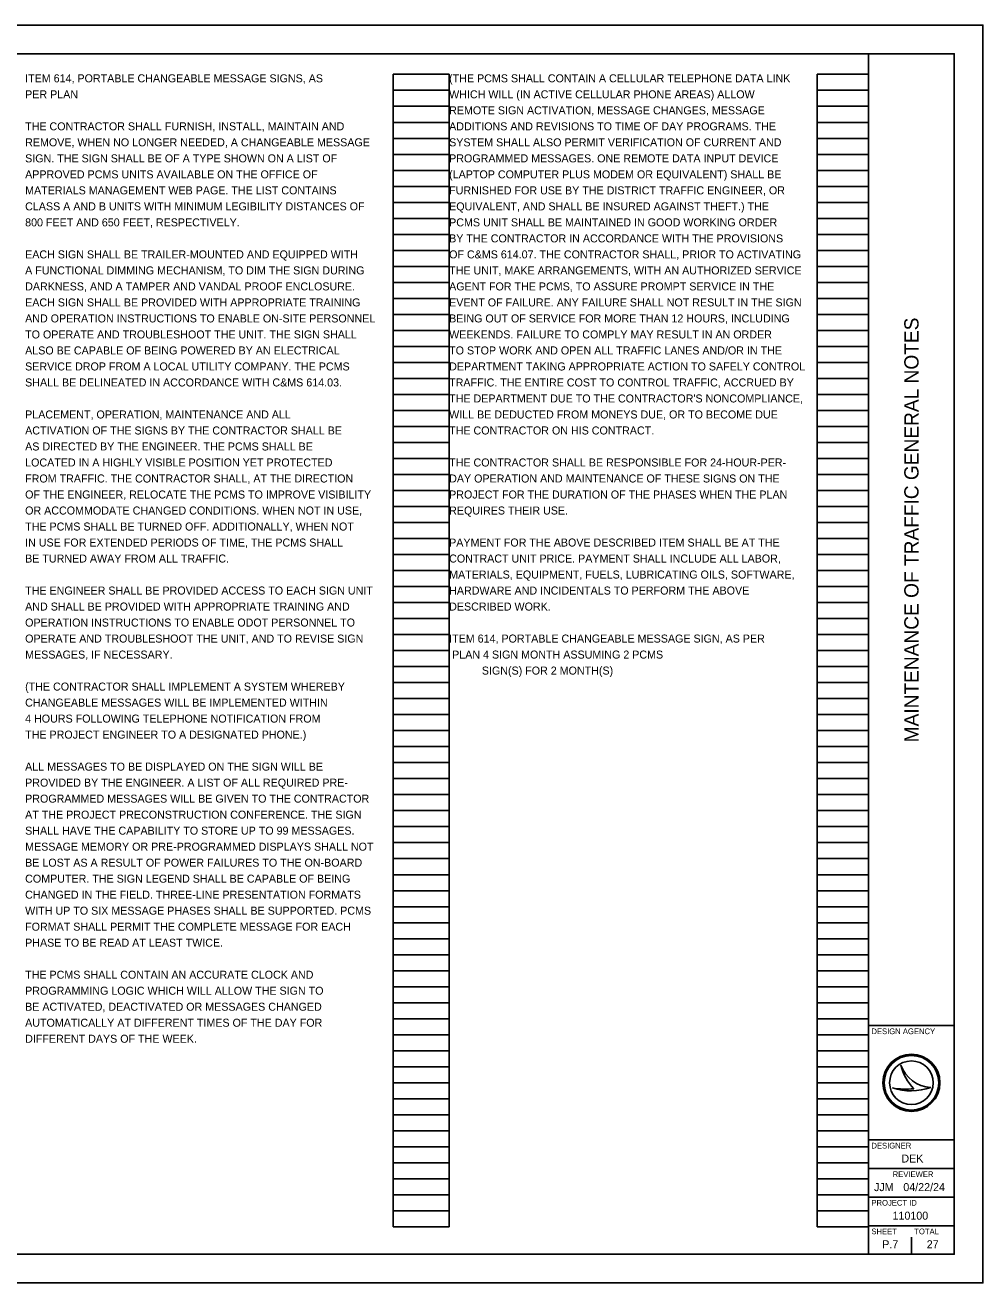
# Model space of a CAD drawing. Extents: x 0 to 34, y 0 to 22.
# Drawn here: x 17.24 to 34, y 0 to 22 of the extents above; entities that cross this region are included whole.
import ezdxf

# ---------------------------------------------------------------- set-up
doc = ezdxf.new("R2010")
doc.units = 0
for name, color, linetype in [('SH_Border', 7, 'Continuous'), ('SH_Cut_Line', 7, 'Continuous'), ('SH_Data', 7, 'Continuous'), ('SH_Text', 7, 'Continuous')]:
    doc.layers.add(name, color=color, linetype=linetype)

msp = doc.modelspace()

# ---------------------------------------------------------------- linework, layer by layer
at = {"layer": 'SH_Border'}
for p, q in [((32, 0.5), (32, 21.5)), ((32, 4.5), (33.5, 4.5)), ((32, 2.5), (33.5, 2.5)), ((32, 2), (33.5, 2)), ((32, 1.5), (33.5, 1.5)), ((32, 1), (33.5, 1))]:
    msp.add_line(p, q, dxfattribs=at)
msp.add_lwpolyline([(1.5, 21.5), (33.5, 21.5), (33.5, 0.5), (1.5, 0.5)], close=True, dxfattribs=at)
at = {"layer": 'SH_Cut_Line'}
msp.add_lwpolyline([(0, 0), (34, 0), (34, 22), (0, 22)], close=True, dxfattribs=at)
at = {"layer": 'SH_Data'}
for p, q in [((23.68, 0.98), (23.68, 21.14)), ((23.68, 21.14), (24.66, 21.14)), ((24.66, 0.98), (24.66, 21.14)), ((31.1, 0.98), (31.1, 21.14)), ((31.1, 21.14), (32, 21.14)), ((32, 0.98), (32, 21.14)), ((23.68, 20.86), (24.66, 20.86)), ((31.1, 20.86), (32, 20.86)), ((23.68, 20.58), (24.66, 20.58)), ((31.1, 20.58), (32, 20.58)), ((23.68, 20.3), (24.66, 20.3)), ((31.1, 20.3), (32, 20.3)), ((23.68, 20.02), (24.66, 20.02)), ((31.1, 20.02), (32, 20.02)), ((23.68, 19.74), (24.66, 19.74)), ((31.1, 19.74), (32, 19.74)), ((23.68, 19.46), (24.66, 19.46)), ((31.1, 19.46), (32, 19.46)), ((23.68, 19.18), (24.66, 19.18)), ((31.1, 19.18), (32, 19.18)), ((23.68, 18.9), (24.66, 18.9)), ((31.1, 18.9), (32, 18.9)), ((23.68, 18.62), (24.66, 18.62)), ((31.1, 18.62), (32, 18.62)), ((23.68, 18.34), (24.66, 18.34)), ((31.1, 18.34), (32, 18.34)), ((23.68, 18.06), (24.66, 18.06)), ((31.1, 18.06), (32, 18.06)), ((23.68, 17.78), (24.66, 17.78)), ((31.1, 17.78), (32, 17.78)), ((23.68, 17.5), (24.66, 17.5)), ((31.1, 17.5), (32, 17.5)), ((23.68, 17.22), (24.66, 17.22)), ((31.1, 17.22), (32, 17.22)), ((23.68, 16.94), (24.66, 16.94)), ((31.1, 16.94), (32, 16.94)), ((23.68, 16.66), (24.66, 16.66)), ((31.1, 16.66), (32, 16.66)), ((23.68, 16.38), (24.66, 16.38)), ((31.1, 16.38), (32, 16.38)), ((23.68, 16.1), (24.66, 16.1)), ((31.1, 16.1), (32, 16.1)), ((23.68, 15.82), (24.66, 15.82)), ((31.1, 15.82), (32, 15.82)), ((23.68, 15.54), (24.66, 15.54)), ((31.1, 15.54), (32, 15.54)), ((23.68, 15.26), (24.66, 15.26)), ((31.1, 15.26), (32, 15.26)), ((23.68, 14.98), (24.66, 14.98)), ((31.1, 14.98), (32, 14.98)), ((23.68, 14.7), (24.66, 14.7)), ((31.1, 14.7), (32, 14.7)), ((23.68, 14.42), (24.66, 14.42)), ((31.1, 14.42), (32, 14.42)), ((23.68, 14.14), (24.66, 14.14)), ((31.1, 14.14), (32, 14.14)), ((23.68, 13.86), (24.66, 13.86)), ((31.1, 13.86), (32, 13.86)), ((23.68, 13.58), (24.66, 13.58)), ((31.1, 13.58), (32, 13.58)), ((23.68, 13.3), (24.66, 13.3)), ((31.1, 13.3), (32, 13.3)), ((23.68, 13.02), (24.66, 13.02)), ((31.1, 13.02), (32, 13.02)), ((23.68, 12.74), (24.66, 12.74)), ((31.1, 12.74), (32, 12.74)), ((23.68, 12.46), (24.66, 12.46)), ((31.1, 12.46), (32, 12.46)), ((23.68, 12.18), (24.66, 12.18)), ((31.1, 12.18), (32, 12.18)), ((23.68, 11.9), (24.66, 11.9)), ((31.1, 11.9), (32, 11.9)), ((23.68, 11.62), (24.66, 11.62)), ((31.1, 11.62), (32, 11.62)), ((23.68, 11.34), (24.66, 11.34)), ((31.1, 11.34), (32, 11.34)), ((23.68, 11.06), (24.66, 11.06)), ((31.1, 11.06), (32, 11.06)), ((23.68, 10.78), (24.66, 10.78)), ((31.1, 10.78), (32, 10.78)), ((23.68, 10.5), (24.66, 10.5)), ((31.1, 10.5), (32, 10.5)), ((23.68, 10.22), (24.66, 10.22)), ((31.1, 10.22), (32, 10.22)), ((23.68, 9.94), (24.66, 9.94)), ((31.1, 9.94), (32, 9.94)), ((23.68, 9.66), (24.66, 9.66)), ((31.1, 9.66), (32, 9.66)), ((23.68, 9.38), (24.66, 9.38)), ((31.1, 9.38), (32, 9.38)), ((23.68, 9.1), (24.66, 9.1)), ((31.1, 9.1), (32, 9.1)), ((23.68, 8.82), (24.66, 8.82)), ((31.1, 8.82), (32, 8.82)), ((23.68, 8.54), (24.66, 8.54)), ((31.1, 8.54), (32, 8.54)), ((23.68, 8.26), (24.66, 8.26)), ((31.1, 8.26), (32, 8.26)), ((23.68, 7.98), (24.66, 7.98)), ((31.1, 7.98), (32, 7.98)), ((23.68, 7.7), (24.66, 7.7)), ((31.1, 7.7), (32, 7.7)), ((23.68, 7.42), (24.66, 7.42)), ((31.1, 7.42), (32, 7.42)), ((23.68, 7.14), (24.66, 7.14)), ((31.1, 7.14), (32, 7.14)), ((23.68, 6.86), (24.66, 6.86)), ((31.1, 6.86), (32, 6.86)), ((23.68, 6.58), (24.66, 6.58)), ((31.1, 6.58), (32, 6.58)), ((23.68, 6.3), (24.66, 6.3)), ((31.1, 6.3), (32, 6.3)), ((23.68, 6.02), (24.66, 6.02)), ((31.1, 6.02), (32, 6.02)), ((23.68, 5.74), (24.66, 5.74)), ((31.1, 5.74), (32, 5.74)), ((23.68, 5.46), (24.66, 5.46)), ((31.1, 5.46), (32, 5.46)), ((23.68, 5.18), (24.66, 5.18)), ((31.1, 5.18), (32, 5.18)), ((23.68, 4.9), (24.66, 4.9)), ((31.1, 4.9), (32, 4.9)), ((23.68, 4.62), (24.66, 4.62)), ((31.1, 4.62), (32, 4.62)), ((23.68, 4.34), (24.66, 4.34)), ((31.1, 4.34), (32, 4.34)), ((23.68, 4.06), (24.66, 4.06)), ((31.1, 4.06), (32, 4.06)), ((23.68, 3.78), (24.66, 3.78)), ((31.1, 3.78), (32, 3.78)), ((32.567, 3.81), (32.567, 3.81)), ((23.68, 3.5), (24.66, 3.5)), ((31.1, 3.5), (32, 3.5)), ((32.417, 3.41), (32.417, 3.41)), ((32.75, 3.5), (32.75, 3.5)), ((33.087, 3.419), (33.087, 3.419)), ((23.68, 3.22), (24.66, 3.22)), ((31.1, 3.22), (32, 3.22)), ((23.68, 2.94), (24.66, 2.94)), ((31.1, 2.94), (32, 2.94)), ((23.68, 2.66), (24.66, 2.66)), ((31.1, 2.66), (32, 2.66)), ((23.68, 2.38), (24.66, 2.38)), ((31.1, 2.38), (32, 2.38)), ((23.68, 2.1), (24.66, 2.1)), ((31.1, 2.1), (32, 2.1)), ((23.68, 1.82), (24.66, 1.82)), ((31.1, 1.82), (32, 1.82)), ((23.68, 1.54), (24.66, 1.54)), ((31.1, 1.54), (32, 1.54)), ((23.68, 1.26), (24.66, 1.26)), ((31.1, 1.26), (32, 1.26)), ((23.68, 0.98), (24.66, 0.98)), ((31.1, 0.98), (32, 0.98)), ((32.375, 0.675), (32.375, 0.675)), ((32.75, 0.5), (32.75, 0.8))]:
    msp.add_line(p, q, dxfattribs=at)
for radius in [0.5, 0.477, 0.477, 0.382]:
    msp.add_circle((32.75, 3.5), radius, dxfattribs=at)
for centre, radius, start, end in [((33.116, 3.998), 0.58, 198.9257, 198.9319), ((33.347, 3.97), 0.796, 191.6379, 191.6421), ((33.116, 3.998), 0.58, 198.9319, 267.1657), ((33.347, 3.97), 0.796, 191.6421, 226.0947), ((32.739, 4.37), 1.013, 251.4576, 290.0832), ((32.648, 4.654), 1.266, 259.4964, 259.4995), ((32.739, 4.37), 1.013, 251.4527, 251.4576), ((32.648, 4.654), 1.266, 259.4995, 276.6672)]:
    msp.add_arc(centre, radius, start, end, dxfattribs=at)

# ---------------------------------------------------------------- texts
msp.add_text('MAINTENANCE OF TRAFFIC GENERAL NOTES', height=0.25, rotation=90, dxfattribs=at).set_placement((32.875, 9.455))
for s, height, p in [('DESIGN AGENCY', 0.1, (32.05, 4.35)), ('DESIGNER', 0.1, (32.05, 2.35)), ('DEK', 0.14, (32.574, 2.105)), ('REVIEWER', 0.1, (32.422, 1.85)), ('JJM', 0.14, (32.095, 1.605)), ('04/22/24', 0.14, (32.608, 1.605)), ('PROJECT ID', 0.1, (32.05, 1.35)), ('110100', 0.14, (32.419, 1.105)), ('SHEET', 0.1, (32.05, 0.85)), ('TOTAL', 0.1, (32.8, 0.85)), ('P.7', 0.14, (32.239, 0.605)), ('27', 0.14, (33.018, 0.605))]:
    msp.add_text(s, height=height, dxfattribs=at).set_placement(p)
at = {"layer": 'SH_Text'}
for s, p in [('ITEM 614, PORTABLE CHANGEABLE MESSAGE SIGNS, AS', (17.24, 21)), ('(THE PCMS SHALL CONTAIN A CELLULAR TELEPHONE DATA LINK', (24.66, 21)), ('PER PLAN', (17.24, 20.72)), ('WHICH WILL (IN ACTIVE CELLULAR PHONE AREAS) ALLOW', (24.66, 20.72)), ('REMOTE SIGN ACTIVATION, MESSAGE CHANGES, MESSAGE', (24.66, 20.44)), ('THE CONTRACTOR SHALL FURNISH, INSTALL, MAINTAIN AND', (17.24, 20.16)), ('ADDITIONS AND REVISIONS TO TIME OF DAY PROGRAMS. THE', (24.66, 20.16)), ('REMOVE, WHEN NO LONGER NEEDED, A CHANGEABLE MESSAGE', (17.24, 19.88)), ('SYSTEM SHALL ALSO PERMIT VERIFICATION OF CURRENT AND', (24.66, 19.88)), ('SIGN. THE SIGN SHALL BE OF A TYPE SHOWN ON A LIST OF', (17.24, 19.6)), ('PROGRAMMED MESSAGES. ONE REMOTE DATA INPUT DEVICE', (24.66, 19.6)), ('APPROVED PCMS UNITS AVAILABLE ON THE OFFICE OF', (17.24, 19.32)), ('(LAPTOP COMPUTER PLUS MODEM OR EQUIVALENT) SHALL BE', (24.66, 19.32)), ('MATERIALS MANAGEMENT WEB PAGE. THE LIST CONTAINS', (17.24, 19.04)), ('FURNISHED FOR USE BY THE DISTRICT TRAFFIC ENGINEER, OR', (24.66, 19.04)), ('CLASS A AND B UNITS WITH MINIMUM LEGIBILITY DISTANCES OF', (17.24, 18.76)), ('EQUIVALENT, AND SHALL BE INSURED AGAINST THEFT.) THE', (24.66, 18.76)), ('800 FEET AND 650 FEET, RESPECTIVELY.', (17.24, 18.48)), ('PCMS UNIT SHALL BE MAINTAINED IN GOOD WORKING ORDER', (24.66, 18.48)), ('BY THE CONTRACTOR IN ACCORDANCE WITH THE PROVISIONS', (24.66, 18.2)), ('EACH SIGN SHALL BE TRAILER-MOUNTED AND EQUIPPED WITH', (17.24, 17.92)), ('OF C&MS 614.07. THE CONTRACTOR SHALL, PRIOR TO ACTIVATING', (24.66, 17.92)), ('A FUNCTIONAL DIMMING MECHANISM, TO DIM THE SIGN DURING', (17.24, 17.64)), ('THE UNIT, MAKE ARRANGEMENTS, WITH AN AUTHORIZED SERVICE', (24.66, 17.64)), ('DARKNESS, AND A TAMPER AND VANDAL PROOF ENCLOSURE.', (17.24, 17.36)), ('AGENT FOR THE PCMS, TO ASSURE PROMPT SERVICE IN THE', (24.66, 17.36)), ('EACH SIGN SHALL BE PROVIDED WITH APPROPRIATE TRAINING', (17.24, 17.08)), ('EVENT OF FAILURE. ANY FAILURE SHALL NOT RESULT IN THE SIGN', (24.66, 17.08)), ('AND OPERATION INSTRUCTIONS TO ENABLE ON-SITE PERSONNEL', (17.24, 16.8)), ('BEING OUT OF SERVICE FOR MORE THAN 12 HOURS, INCLUDING', (24.66, 16.8)), ('TO OPERATE AND TROUBLESHOOT THE UNIT. THE SIGN SHALL', (17.24, 16.52)), ('WEEKENDS. FAILURE TO COMPLY MAY RESULT IN AN ORDER', (24.66, 16.52)), ('ALSO BE CAPABLE OF BEING POWERED BY AN ELECTRICAL', (17.24, 16.24)), ('TO STOP WORK AND OPEN ALL TRAFFIC LANES AND/OR IN THE', (24.66, 16.24)), ('SERVICE DROP FROM A LOCAL UTILITY COMPANY. THE PCMS', (17.24, 15.96)), ('DEPARTMENT TAKING APPROPRIATE ACTION TO SAFELY CONTROL', (24.66, 15.96)), ('SHALL BE DELINEATED IN ACCORDANCE WITH C&MS 614.03.', (17.24, 15.68)), ('TRAFFIC. THE ENTIRE COST TO CONTROL TRAFFIC, ACCRUED BY', (24.66, 15.68)), ("THE DEPARTMENT DUE TO THE CONTRACTOR'S NONCOMPLIANCE,", (24.66, 15.4)), ('PLACEMENT, OPERATION, MAINTENANCE AND ALL', (17.24, 15.12)), ('WILL BE DEDUCTED FROM MONEYS DUE, OR TO BECOME DUE', (24.66, 15.12)), ('ACTIVATION OF THE SIGNS BY THE CONTRACTOR SHALL BE', (17.24, 14.84)), ('THE CONTRACTOR ON HIS CONTRACT.', (24.66, 14.84)), ('AS DIRECTED BY THE ENGINEER. THE PCMS SHALL BE', (17.24, 14.56)), ('LOCATED IN A HIGHLY VISIBLE POSITION YET PROTECTED', (17.24, 14.28)), ('THE CONTRACTOR SHALL BE RESPONSIBLE FOR 24-HOUR-PER-', (24.66, 14.28)), ('FROM TRAFFIC. THE CONTRACTOR SHALL, AT THE DIRECTION', (17.24, 14)), ('DAY OPERATION AND MAINTENANCE OF THESE SIGNS ON THE', (24.66, 14)), ('OF THE ENGINEER, RELOCATE THE PCMS TO IMPROVE VISIBILITY', (17.24, 13.72)), ('PROJECT FOR THE DURATION OF THE PHASES WHEN THE PLAN', (24.66, 13.72)), ('OR ACCOMMODATE CHANGED CONDITIONS. WHEN NOT IN USE,', (17.24, 13.44)), ('REQUIRES THEIR USE.', (24.66, 13.44)), ('THE PCMS SHALL BE TURNED OFF. ADDITIONALLY, WHEN NOT', (17.24, 13.16)), ('IN USE FOR EXTENDED PERIODS OF TIME, THE PCMS SHALL', (17.24, 12.88)), ('PAYMENT FOR THE ABOVE DESCRIBED ITEM SHALL BE AT THE', (24.66, 12.88)), ('BE TURNED AWAY FROM ALL TRAFFIC.', (17.24, 12.6)), ('CONTRACT UNIT PRICE. PAYMENT SHALL INCLUDE ALL LABOR,', (24.66, 12.6)), ('MATERIALS, EQUIPMENT, FUELS, LUBRICATING OILS, SOFTWARE,', (24.66, 12.32)), ('THE ENGINEER SHALL BE PROVIDED ACCESS TO EACH SIGN UNIT', (17.24, 12.04)), ('HARDWARE AND INCIDENTALS TO PERFORM THE ABOVE', (24.66, 12.04)), ('AND SHALL BE PROVIDED WITH APPROPRIATE TRAINING AND', (17.24, 11.76)), ('DESCRIBED WORK.', (24.66, 11.76)), ('OPERATION INSTRUCTIONS TO ENABLE ODOT PERSONNEL TO', (17.24, 11.48)), ('OPERATE AND TROUBLESHOOT THE UNIT, AND TO REVISE SIGN', (17.24, 11.2)), ('ITEM 614, PORTABLE CHANGEABLE MESSAGE SIGN, AS PER', (24.66, 11.2)), ('MESSAGES, IF NECESSARY.', (17.24, 10.92)), (' PLAN 4 SIGN MONTH ASSUMING 2 PCMS', (24.66, 10.92)), ('           SIGN(S) FOR 2 MONTH(S)', (24.66, 10.64)), ('(THE CONTRACTOR SHALL IMPLEMENT A SYSTEM WHEREBY', (17.24, 10.36)), ('CHANGEABLE MESSAGES WILL BE IMPLEMENTED WITHIN', (17.24, 10.08)), ('4 HOURS FOLLOWING TELEPHONE NOTIFICATION FROM', (17.24, 9.8)), ('THE PROJECT ENGINEER TO A DESIGNATED PHONE.)', (17.24, 9.52)), ('ALL MESSAGES TO BE DISPLAYED ON THE SIGN WILL BE', (17.24, 8.96)), ('PROVIDED BY THE ENGINEER. A LIST OF ALL REQUIRED PRE-', (17.24, 8.68)), ('PROGRAMMED MESSAGES WILL BE GIVEN TO THE CONTRACTOR', (17.24, 8.4)), ('AT THE PROJECT PRECONSTRUCTION CONFERENCE. THE SIGN', (17.24, 8.12)), ('SHALL HAVE THE CAPABILITY TO STORE UP TO 99 MESSAGES.', (17.24, 7.84)), ('MESSAGE MEMORY OR PRE-PROGRAMMED DISPLAYS SHALL NOT', (17.24, 7.56)), ('BE LOST AS A RESULT OF POWER FAILURES TO THE ON-BOARD', (17.24, 7.28)), ('COMPUTER. THE SIGN LEGEND SHALL BE CAPABLE OF BEING', (17.24, 7)), ('CHANGED IN THE FIELD. THREE-LINE PRESENTATION FORMATS', (17.24, 6.72)), ('WITH UP TO SIX MESSAGE PHASES SHALL BE SUPPORTED. PCMS', (17.24, 6.44)), ('FORMAT SHALL PERMIT THE COMPLETE MESSAGE FOR EACH', (17.24, 6.16)), ('PHASE TO BE READ AT LEAST TWICE.', (17.24, 5.88)), ('THE PCMS SHALL CONTAIN AN ACCURATE CLOCK AND', (17.24, 5.32)), ('PROGRAMMING LOGIC WHICH WILL ALLOW THE SIGN TO', (17.24, 5.04)), ('BE ACTIVATED, DEACTIVATED OR MESSAGES CHANGED', (17.24, 4.76)), ('AUTOMATICALLY AT DIFFERENT TIMES OF THE DAY FOR', (17.24, 4.48)), ('DIFFERENT DAYS OF THE WEEK.', (17.24, 4.2))]:
    msp.add_text(s, height=0.14, dxfattribs=at).set_placement(p)

doc.saveas('drawing.dxf')
